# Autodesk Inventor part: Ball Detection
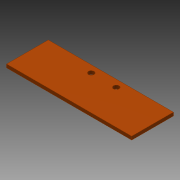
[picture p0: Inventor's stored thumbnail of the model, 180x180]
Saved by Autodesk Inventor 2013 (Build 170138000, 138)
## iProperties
Created: 2012-08
Part Number: Ball Detection
Material: Phenolharz
Document SubType Name: Modeling
Designer: rYan
Mass: 2.62432 g
Surface Area: 26.6024 cm^2
Volume: 1.90168 cm^3
Density: 1.38 g/cm^3
Author: rYan
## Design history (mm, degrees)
sketch "Skizze1"
  geometry: L1 (-30, 10)-(30, 10); L2 (30, 10)-(30, -10); L3 (30, -10)-(-30, -10); L4 (-30, -10)-(-30, 10); L5 (-42, 0)-(42, 0) reference; L6 (0, 14)-(0, -14) reference; 1 further point
  constraints: 8 end point, 2 parallel, 1 horizontal, 1 perpendicular, 2 other
  dimensions: "d0" = 20 distance of L3.end L1.start; "d2" = 60 distance of L1.start L1.end
extrude "Extrusion1" new body sketch "Skizze1" distance "d3" = 1.6; taper "d4" = 0 deg
sketch "Skizze2"
  geometry: L1 (0, 14)-(0, -14) reference; L2 (-42, 0)-(42, 0) reference; L3 (-6, 6.6)-(6, 6.6); 1 further point
  constraints: 2 end point, 1 parallel, 1 symmetric about line
  dimensions: "d5" = 12 distance of L3.start L3.end; "d7" = 6.6 distance between parallel lines of L2 L3
hole "Bohrung1" sketch "Skizze2" at (-6, 6.6), (6, 6.6) diameter "d8" = 2.7; stored, may be unused: countersink angle "d12" = 90 deg, drill point angle "d14" = 118 deg; dims "d9" = 6, "d10" = 4, "d11" = 2, "d13" = 8
node "Volumenkörper1"
